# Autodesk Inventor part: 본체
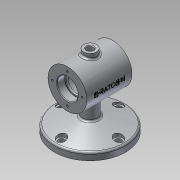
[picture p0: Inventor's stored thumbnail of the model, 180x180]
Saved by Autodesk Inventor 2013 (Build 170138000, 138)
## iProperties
Created: 2018-12
Part Number: 본체
Material: 알루미늄 6061
Document SubType Name: Modeling
Designer: Administrator
Density: 2.71 g/cm^3
Mass: 687.672 g
Surface Area: 555.63 cm^2
Volume: 253.753 cm^3
Author: Administrator
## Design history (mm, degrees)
sketch "스케치1"
  geometry: L1 (-35, 0)-(35, 0); L2 (-35, 16)-(-35, 30); L3 (-35, 30)-(35, 30); L4 (35, 30)-(35, 16); L5 (-35, 16)-(-23, 16); L6 (-23, 16)-(-23, 14); L7 (-23, 14)-(-20, 14); L8 (-20, 14)-(-20, 25); L9 (-20, 25)-(20, 25); L10 (20, 25)-(20, 14); L11 (20, 14)-(23, 14); L12 (23, 14)-(23, 16); L13 (23, 16)-(35, 16); 1 further point
  constraints: 26 end point, 6 parallel, 5 perpendicular, 2 collinear, 2 point on line, 1 horizontal, 1 midpoint, 1 vertical
  dimensions: "d0" = 70 distance of L1.start L1.end; "d2" = 35 distance of point (0, 0) L1.start; "d3" = 60 diameter of L3 L1; "d5" = 32 diameter of L5 L1; "d6" = 50 diameter of L9 L1; "d7" = 28 diameter of L7 L1; "d8" = 12 distance between parallel lines of L2 L6; "d9" = 3 distance between parallel lines of L8 L6; "d10" = 3 distance between parallel lines of L12 L10; "d11" = 12 distance between parallel lines of L4 L12
revolve "회전1" sketch "스케치1" stored, may be unused: angle "d12" = 90 deg
node "작업 평면1"
sketch "스케치2"
  geometry: L1 (35, 30)-(35, -30) reference; C1 r 10 at (0, 0); 1 further point
  constraints: 1 centre point, 1 coincident
  dimensions: "d14" = 35 distance from line of L1 C1.centre; "d15" = 20 diameter of C1
extrude "돌출1" join sketch "스케치2" stored distance "d16" = 10; taper "d17" = 0 deg
hole "구멍1" diameter "d20" = 10; stored, may be unused: countersink angle "d24" = 90 deg, drill point angle "d26" = 0 deg; dims "d18" = 10, "d19" = 10, "d21" = 6, "d22" = 4, "d23" = 2, "d25" = 8
sketch "스케치3"
  geometry: L1 (-75, 55)-(-64, 55); L2 (-64, 55)-(-52.478, 12); L3 (-30, 0)-(-75, 0); L4 (-75, 55)-(-75, 0); L5 (37, 10)-(37, -10) reference; L6 (-52.478, 12)-(-27.495, 12); A1 r 30 centre (0, 0) between (-30, 0) and (-27.495, 12) reference; A2 r 25 centre (0, 0) between (-21.932, 12) and (-25, 0) reference; 1 further point
  constraints: 10 end point, 4 point on circle, 2 perpendicular, 1 point on line
  dimensions: "d29" = 110 diameter of L1 L3; "d31" = 75 deg angle of L2 L1; "d33" = 75 distance from line of L4 point (0, 0); "d34" = 11 distance of L1.start L1.end; "d35" = 112 distance between parallel lines of L4 L5 (derived); "d37" = 24 diameter of L6 L3
revolve "회전2" sketch "스케치3" stored, may be unused: angle "d36" = 90 deg
sketch "스케치5"
  geometry: C1 r 16 at (0, 0) reference; 1 further point
  constraints: 1 vertical alignment
  dimensions: "d38" = 23 distance of C1.centre point (0, 23)
hole "구멍2" sketch "스케치5" at (0, 23) diameter "d39" = 3.242; stored, may be unused: countersink angle "d43" = 90 deg, drill point angle "d45" = 118 deg; dims "d40" = 8, "d41" = 4, "d42" = 2, "d44" = 10
sketch "스케치6"
  geometry: C1 r 55 at (0, 0) reference; C2 r 4.5 at (44, 0)
  constraints: 1 centre point, 1 horizontal alignment
  dimensions: "d49" = 44 distance of C1.centre C2.centre; "d50" = 9 diameter of C2
extrude "돌출2" cut sketch "스케치6" distance "d51" = 10; taper "d52" = 0 deg
hole "구멍3" diameter "d55" = 14; stored, may be unused: countersink angle "d59" = 90 deg, drill point angle "d61" = 0 deg; dims "d53" = 10, "d54" = 10, "d56" = 8, "d57" = 4, "d58" = 2, "d60" = 10
fillet "모깎기1" dims "d65" = 3
fillet "모깎기2" dims "d66" = 0.3
fillet "모깎기3" dims "d67" = 3
chamfer "모따기1" distance "d68" = 1; stored, may be unused: second distance "d69" = 2, angle "d70" = 45 deg
sketch "스케치7"
  geometry: L1 (0, 0)-(0, 30); 1 further point
  constraints: 2 end point, 1 vertical, 1 vertical alignment, 1 other
node "작업 평면2"
sketch "스케치8"
  geometry: L1 (-35, -30)-(-35, 30) reference; L2 (-35, 30)-(35, 30) reference; 2 further points
  constraints: 1 other
  dimensions: "d71" = 35 distance from line of point (0, 0) L1; "d72" = 30 distance from line of point (0, 0) L2
feature "엠보싱1" sketch "스케치8" dims "d0" = 70, "d2" = 35, "d3" = 60, "d5" = 32, "d6" = 50, "d7" = 28, "d8" = 12, "d9" = 3, "d10" = 3, "d11" = 12, "d73" = 0.5, "d74" = 0
chamfer "모따기2" distance "d75" = 1; stored, may be unused: second distance "d76" = 2, angle "d77" = 45 deg
node "솔리드1"
pattern_circular "원형 패턴1" dims angle "d47" = 360 deg
mirror "대칭1"
pattern_circular "원형 패턴2" dims angle "d63" = 360 deg
other parameters: "d13" = 37
